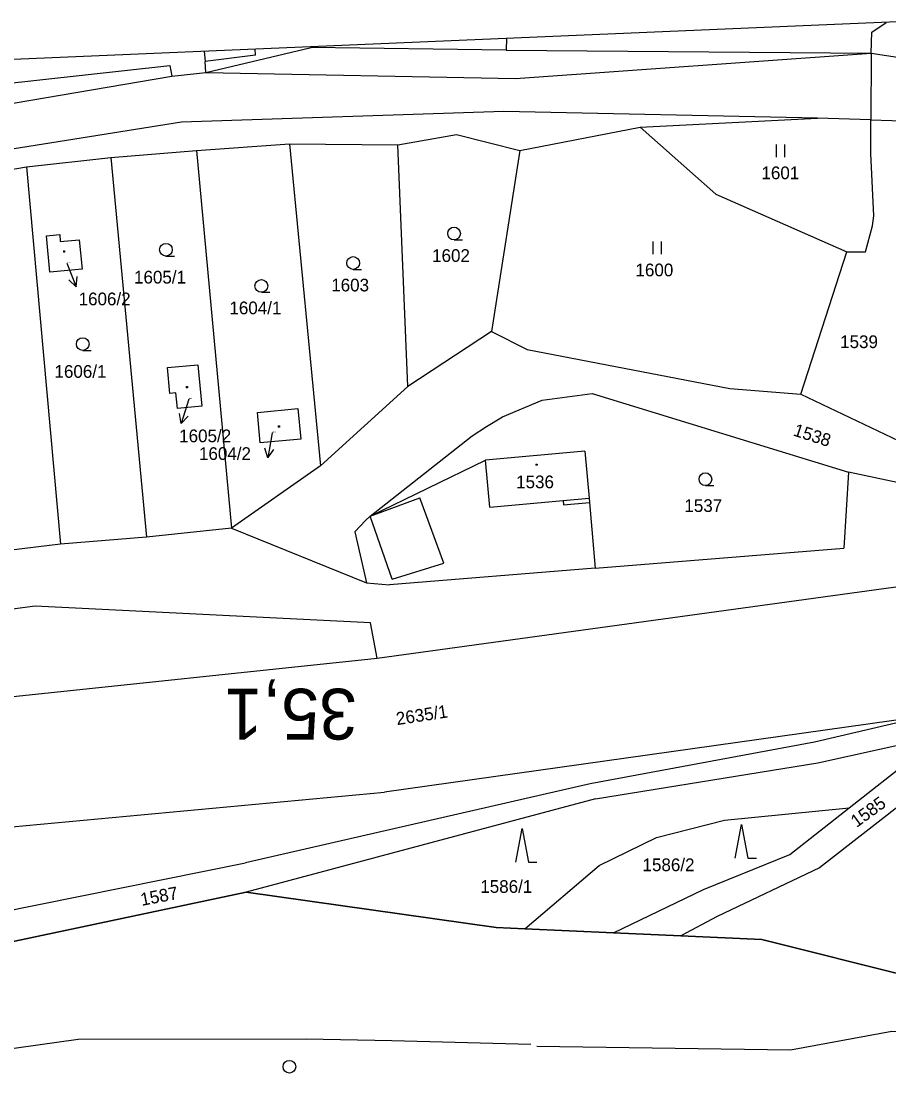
# Model space of a CAD drawing. Extents: x -806456 to -805395, y -1150847 to -1150506.
# Drawn here: x -805932.5 to -805830, y -1150648.6 to -1150523.9 of the extents above; entities that cross this region are included whole.
import ezdxf

# ---------------------------------------------------------------- set-up
doc = ezdxf.new("R2010")
doc.units = 0
for name, color, linetype in [('Default', 7, 'Continuous'), ('formát', 7, 'Continuous'), ('kilometráž - vrstava 7', 7, 'Continuous'), ('kn_celek - Cisla parcel pomocna', 7, 'Continuous'), ('kn_celek - Cisla pozemkovych parcel', 7, 'Continuous'), ('kn_celek - Cisla stavebnich parcel', 7, 'Continuous'), ('kn_celek - Hranice parcel', 7, 'Continuous'), ('kn_celek - Vnitrni kresby', 7, 'Continuous'), ('kn_celek - Znacky budov', 7, 'Continuous'), ('kn_celek - Znacky kultur', 7, 'Continuous'), ('plochy - SZDC', 7, 'Continuous'), ('PSR_C2_2_trasa_Vimperk - Kabelová trasa', 7, 'Continuous')]:
    doc.layers.add(name, color=color, linetype=linetype)

# ---------------------------------------------------------------- blocks, each defined once
blk = doc.blocks.new('304')
at = {"layer": 'Default'}
blk.add_line((-0.1, 0), (9.9, 0), dxfattribs=at)
blk.add_circle((-0.1, 7.5), 7.5, dxfattribs=at)
blk = doc.blocks.new('306')
at = {"layer": 'Default'}
for p, q in [((-5.2, 0), (-5.2, 15)), ((4.8, 0), (4.8, 15))]:
    blk.add_line(p, q, dxfattribs=at)
blk = doc.blocks.new('308')
at = {"layer": 'Default'}
for p, q in [((-7.5, 0.2), (0, 40.2)), ((0, 40.2), (7.5, 0.2)), ((7.5, 0.2), (17.5, 0.2))]:
    blk.add_line(p, q, dxfattribs=at)
blk = doc.blocks.new('402')
at = {"layer": 'Default'}
for p, q in [((-0.8, 0.8), (0.7, 0.8)), ((-0.8, 0.8), (-0.8, -0.7)), ((0.7, 0.8), (0.7, -0.7)), ((0.7, -0.7), (-0.8, -0.7))]:
    blk.add_line(p, q, dxfattribs=at)
blk = doc.blocks.new('Z61')
at = {"layer": 'Default'}
for p, q in [((0, 0), (30, 0)), ((30, 0), (19.2, 5.3)), ((30, 0), (19.2, -5.3))]:
    blk.add_line(p, q, dxfattribs=at)

msp = doc.modelspace()

# ---------------------------------------------------------------- linework, layer by layer
at = {"layer": 'formát'}
msp.add_line((-805826.83, -1150523.88), (-806456.26, -1150550.6), dxfattribs=at)
at = {"layer": 'kilometráž - vrstava 7'}
msp.add_circle((-805900.8, -1150647.27), 0.75, dxfattribs=at)
at = {"layer": 'kn_celek - Hranice parcel'}
for p, q in [((-805832.05, -1150525.18), (-805830.35, -1150524.03)), ((-805875.18, -1150525.93), (-805875.21, -1150527.3)), ((-805832.14, -1150527.65), (-805832.05, -1150525.18)), ((-805910.66, -1150529.92), (-805898.23, -1150527)), ((-805904.81, -1150527.91), (-805904.86, -1150527.19)), ((-805875.21, -1150527.3), (-805898.23, -1150527)), ((-805875.21, -1150527.3), (-805832.14, -1150527.65)), ((-805904.81, -1150527.91), (-805910.75, -1150528.65)), ((-805832.14, -1150527.65), (-805825.89, -1150528.63)), ((-805910.66, -1150529.92), (-805910.75, -1150528.65)), ((-805946.48, -1150535.78), (-805914.7, -1150530.39)), ((-805914.7, -1150530.39), (-805910.66, -1150529.92)), ((-805859.4, -1150536.38), (-805838.48, -1150535.31)), ((-805832.18, -1150535.52), (-805838.48, -1150535.31)), ((-805832.15, -1150539.48), (-805832.18, -1150535.52)), ((-805832.18, -1150535.52), (-805825.94, -1150535.7)), ((-805888, -1150538.46), (-805881.07, -1150537.25)), ((-805881.07, -1150537.25), (-805873.61, -1150539.14)), ((-805873.61, -1150539.14), (-805859.4, -1150536.38)), ((-805859.4, -1150536.38), (-805850.46, -1150544.3)), ((-805911.77, -1150539.16), (-805900.81, -1150538.37)), ((-805900.81, -1150538.37), (-805897.13, -1150576.36)), ((-805900.81, -1150538.37), (-805888, -1150538.46)), ((-805886.84, -1150567), (-805888, -1150538.46)), ((-805921.9, -1150539.98), (-805911.77, -1150539.16)), ((-805911.77, -1150539.16), (-805907.66, -1150583.7)), ((-805873.61, -1150539.14), (-805876.96, -1150560.52)), ((-805831.8, -1150546.87), (-805832.15, -1150539.48)), ((-805931.86, -1150541.09), (-805921.9, -1150539.98)), ((-805921.9, -1150539.98), (-805917.69, -1150584.76)), ((-805941.33, -1150542.63), (-805931.86, -1150541.09)), ((-805931.86, -1150541.09), (-805927.83, -1150585.59)), ((-805850.46, -1150544.3), (-805835.02, -1150551.11)), ((-805831.96, -1150548.04), (-805831.8, -1150546.87)), ((-805832.8, -1150551.11), (-805831.96, -1150548.04)), ((-805929.49, -1150549.2), (-805927.9, -1150549.05)), ((-805929.08, -1150553.52), (-805929.49, -1150549.2)), ((-805927.9, -1150549.05), (-805927.87, -1150549.89)), ((-805927.87, -1150549.89), (-805925.63, -1150549.68)), ((-805925.63, -1150549.68), (-805925.28, -1150553.16)), ((-805840.43, -1150567.9), (-805835.02, -1150551.11)), ((-805835.02, -1150551.11), (-805832.8, -1150551.11)), ((-805925.28, -1150553.16), (-805929.08, -1150553.52)), ((-805876.96, -1150560.52), (-805886.84, -1150567)), ((-805876.96, -1150560.52), (-805872.72, -1150562.63)), ((-805872.72, -1150562.63), (-805848.81, -1150567.21)), ((-805915.2, -1150564.77), (-805911.62, -1150564.44)), ((-805911.62, -1150564.44), (-805911.16, -1150569.31)), ((-805914.91, -1150567.8), (-805915.2, -1150564.77)), ((-805886.84, -1150567), (-805897.13, -1150576.36)), ((-805914.2, -1150567.74), (-805914.91, -1150567.8)), ((-805914.03, -1150569.58), (-805914.2, -1150567.74)), ((-805870.96, -1150568.6), (-805865.05, -1150567.81)), ((-805865.05, -1150567.81), (-805834.82, -1150577.09)), ((-805848.81, -1150567.21), (-805840.43, -1150567.9)), ((-805840.43, -1150567.9), (-805828.85, -1150573.42)), ((-805911.16, -1150569.31), (-805914.03, -1150569.58)), ((-805904.59, -1150570.05), (-805899.8, -1150569.59)), ((-805899.8, -1150569.59), (-805899.44, -1150573.2)), ((-805875.67, -1150570.57), (-805870.96, -1150568.6)), ((-805904.24, -1150573.66), (-805904.59, -1150570.05)), ((-805877.54, -1150571.7), (-805875.67, -1150570.57)), ((-805879.24, -1150572.83), (-805877.54, -1150571.7)), ((-805899.44, -1150573.2), (-805904.24, -1150573.66)), ((-805891.29, -1150582.28), (-805879.24, -1150572.83)), ((-805865.92, -1150574.62), (-805877.66, -1150575.69)), ((-805865.92, -1150574.62), (-805865.42, -1150580.16)), ((-805891.29, -1150582.28), (-805877.66, -1150575.69)), ((-805897.13, -1150576.36), (-805907.66, -1150583.7)), ((-805834.82, -1150577.09), (-805835.35, -1150586.06)), ((-805817.33, -1150580.82), (-805834.82, -1150577.09)), ((-805865.42, -1150580.16), (-805865.37, -1150580.69)), ((-805865.37, -1150580.69), (-805864.73, -1150588.43)), ((-805893.1, -1150584.16), (-805891.81, -1150582.82)), ((-805891.81, -1150582.82), (-805891.29, -1150582.28)), ((-805907.66, -1150583.7), (-805917.69, -1150584.76)), ((-805907.66, -1150583.7), (-805891.71, -1150590.17)), ((-805893.1, -1150584.16), (-805891.71, -1150590.17)), ((-805927.83, -1150585.59), (-805938.4, -1150586.88)), ((-805917.69, -1150584.76), (-805927.83, -1150585.59)), ((-805890.43, -1150599.04), (-805797.14, -1150586.21)), ((-805864.73, -1150588.43), (-805835.35, -1150586.06)), ((-805864.73, -1150588.43), (-805888.99, -1150590.38)), ((-805891.71, -1150590.17), (-805888.99, -1150590.38)), ((-805930.82, -1150592.93), (-805944.13, -1150594.65)), ((-805891.22, -1150594.87), (-805930.82, -1150592.93)), ((-805890.43, -1150599.04), (-805891.22, -1150594.87)), ((-805990.21, -1150609.59), (-805890.43, -1150599.04)), ((-805825.39, -1150605.82), (-805889.59, -1150614.88)), ((-805825.39, -1150605.82), (-805838.83, -1150608.98)), ((-805838.44, -1150611.4), (-805823.93, -1150608.21)), ((-805834.72, -1150616.72), (-805823.93, -1150608.21)), ((-805838.83, -1150608.98), (-805865.32, -1150613.87)), ((-805864.66, -1150615.66), (-805838.44, -1150611.4)), ((-805821.59, -1150610.86), (-805838.24, -1150623.79)), ((-805865.32, -1150613.87), (-805906.01, -1150623.2)), ((-805991.42, -1150624.34), (-805889.59, -1150614.88)), ((-805864.66, -1150615.66), (-805905.92, -1150626.68)), ((-805849.46, -1150618.19), (-805834.72, -1150616.72)), ((-805841.72, -1150622.24), (-805834.72, -1150616.72)), ((-805857.48, -1150620.23), (-805849.46, -1150618.19)), ((-805864.24, -1150623.53), (-805857.48, -1150620.23)), ((-805955.67, -1150633.22), (-805906.01, -1150623.2)), ((-805851.91, -1150626.36), (-805841.72, -1150622.24)), ((-805873.01, -1150630.99), (-805864.24, -1150623.53)), ((-805838.24, -1150623.79), (-805850.31, -1150629.54)), ((-805936.34, -1150633.1), (-805905.92, -1150626.68)), ((-805905.92, -1150626.68), (-805876.4, -1150630.84)), ((-805862.56, -1150631.46), (-805851.91, -1150626.36)), ((-805850.31, -1150629.54), (-805854.6, -1150631.81)), ((-805876.4, -1150630.84), (-805873.01, -1150630.99)), ((-805873.01, -1150630.99), (-805862.56, -1150631.46)), ((-805862.56, -1150631.46), (-805854.6, -1150631.81)), ((-805854.6, -1150631.81), (-805845.04, -1150632.24)), ((-805845.04, -1150632.24), (-805827.46, -1150636.65))]:
    msp.add_line(p, q, dxfattribs=at)
at = {"layer": 'kn_celek - Vnitrni kresby'}
for p, q in [((-805910.88, -1150527.44), (-805910.75, -1150528.65)), ((-805874.1, -1150530.63), (-805832.14, -1150527.65)), ((-805832.14, -1150527.65), (-805832.18, -1150535.52)), ((-805946.77, -1150532.62), (-805914.93, -1150529.1)), ((-805914.93, -1150529.1), (-805914.7, -1150530.39)), ((-805910.66, -1150529.92), (-805874.1, -1150530.63)), ((-805875.5, -1150534.53), (-805913.56, -1150535.79)), ((-805838.48, -1150535.31), (-805875.5, -1150534.53)), ((-805913.56, -1150535.79), (-805961.29, -1150543.38)), ((-805877.16, -1150581.23), (-805877.66, -1150575.69)), ((-805891.29, -1150582.28), (-805885.4, -1150580.13)), ((-805882.59, -1150587.85), (-805885.4, -1150580.13)), ((-805877.16, -1150581.23), (-805868.5, -1150580.44)), ((-805868.5, -1150580.44), (-805865.42, -1150580.16)), ((-805868.5, -1150580.44), (-805868.45, -1150580.97)), ((-805868.45, -1150580.97), (-805865.37, -1150580.69)), ((-805888.66, -1150589.73), (-805891.29, -1150582.28)), ((-805888.66, -1150589.73), (-805882.59, -1150587.85))]:
    msp.add_line(p, q, dxfattribs=at)
at = {"layer": 'plochy - SZDC'}
for p, q in [((-805905.92, -1150626.68), (-805936.34, -1150633.1)), ((-805876.4, -1150630.84), (-805905.92, -1150626.68)), ((-805873.01, -1150630.99), (-805876.4, -1150630.84)), ((-805862.56, -1150631.46), (-805873.01, -1150630.99)), ((-805854.6, -1150631.81), (-805862.56, -1150631.46)), ((-805845.04, -1150632.24), (-805854.6, -1150631.81)), ((-805827.46, -1150636.65), (-805845.04, -1150632.24))]:
    msp.add_line(p, q, dxfattribs=at)
at = {"layer": 'PSR_C2_2_trasa_Vimperk - Kabelová trasa'}
for p, q in [((-805925.76, -1150644.05), (-805945.75, -1150646.88)), ((-805872.29, -1150644.65), (-805888.73, -1150644.23))]:
    msp.add_line(p, q, dxfattribs=at)
for points in [[(-805871.58, -1150644.84), (-805841.67, -1150645.26), (-805829.69, -1150643.07), (-805746.23, -1150646.95), (-805734.34, -1150648.12), (-805727.43, -1150648.58), (-805708.99, -1150648.44)], [(-805888.73, -1150644.23), (-805898.84, -1150644.02), (-805925.76, -1150644.05)]]:
    msp.add_lwpolyline(points, dxfattribs=at)

# ---------------------------------------------------------------- block references
at = {"layer": 'kn_celek - Cisla parcel pomocna'}
for p, xscale, yscale, rotation in [((-805927.08, -1150552.43), 0.10000000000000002, 0.1, -68.19866999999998), ((-805912.7, -1150568.49), 0.10000000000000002, 0.1, -107.35397999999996), ((-805902.86, -1150572.46), 0.1, 0.10000000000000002, -99.46223999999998)]:
    msp.add_blockref('Z61', p, dxfattribs=dict(at, xscale=xscale, yscale=yscale, rotation=rotation))
at = {"layer": 'kn_celek - Znacky budov', "xscale": 0.1, "yscale": 0.10000000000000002}
for p in [(-805927.41, -1150551.06), (-805912.91, -1150567.09), (-805902.04, -1150571.71), (-805871.64, -1150576.22)]:
    msp.add_blockref('402', p, dxfattribs=at)
at = {"layer": 'kn_celek - Znacky kultur', "xscale": 0.1, "yscale": 0.10000000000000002}
for name, p in [('306', (-805842.8, -1150539.93)), ('304', (-805881.36, -1150549.69)), ('304', (-805915.37, -1150551.61)), ('306', (-805857.35, -1150551.39)), ('304', (-805893.27, -1150553.17)), ('304', (-805904.11, -1150555.87)), ('304', (-805925.19, -1150562.74)), ('304', (-805851.69, -1150578.68)), ('308', (-805873.33, -1150623.16)), ('308', (-805847.43, -1150622.69))]:
    msp.add_blockref(name, p, dxfattribs=at)

# ---------------------------------------------------------------- texts
at = {"layer": 'kilometráž - vrstava 7'}
msp.add_text('35,1', height=6, rotation=180, dxfattribs=at).set_placement((-805892.83, -1150602.66))
at = {"layer": 'kn_celek - Cisla parcel pomocna'}
for s, p in [('1606/2', (-805925.69, -1150557.41)), ('1605/2', (-805913.82, -1150573.57)), ('1604/2', (-805911.48, -1150575.66))]:
    msp.add_text(s, height=1.5, dxfattribs=at).set_placement(p)
at = {"layer": 'kn_celek - Cisla pozemkovych parcel'}
for s, p in [('1601', (-805845.08, -1150542.53)), ('1602', (-805883.96, -1150552.29)), ('1605/1', (-805919.15, -1150554.84)), ('1600', (-805859.95, -1150553.99)), ('1603', (-805895.87, -1150555.77)), ('1604/1', (-805907.89, -1150558.47)), ('1539', (-805835.79, -1150562.46)), ('1606/1', (-805928.54, -1150565.97)), ('1537', (-805854.18, -1150581.8)), ('1586/2', (-805859.12, -1150624.19)), ('1586/1', (-805878.27, -1150626.75))]:
    msp.add_text(s, height=1.5, dxfattribs=at).set_placement(p)
for s, rotation, p in [('1538', 342, (-805841.43, -1150572.76)), ('2635/1', 8.6544, (-805888.1, -1150606.96)), ('1585', 36, (-805833.85, -1150619.1)), ('1587', 10.8, (-805918.24, -1150628.29))]:
    msp.add_text(s, height=1.5, rotation=rotation, dxfattribs=at).set_placement(p)
at = {"layer": 'kn_celek - Cisla stavebnich parcel'}
for s, height, p in [('1606/2', 0.1, (-805927.08, -1150552.4)), ('1605/2', 0.1, (-805912.7, -1150568.46)), ('1604/2', 0.1, (-805902.86, -1150572.43)), ('1536', 1.5, (-805874.04, -1150579))]:
    msp.add_text(s, height=height, dxfattribs=at).set_placement(p)

doc.saveas('drawing.dxf')
